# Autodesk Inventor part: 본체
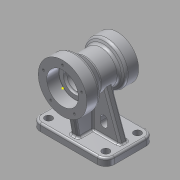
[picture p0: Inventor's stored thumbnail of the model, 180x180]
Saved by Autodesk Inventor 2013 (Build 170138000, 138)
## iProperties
Created: 2015-08
Part Number: 본체
Material: 알루미늄 6061
Document SubType Name: Modeling
Designer: ST4
Density: 2.71 g/cm^3
Mass: 1055 g
Surface Area: 768.882 cm^2
Volume: 389.298 cm^3
Author: ST4
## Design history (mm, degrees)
sketch "스케치1"
  geometry: 1 further point
sketch "스케치2"
  geometry: L1 (0, 0)-(90, 0); L2 (0, 26)-(0, 40); L3 (0, 40)-(20, 40); L4 (20, 40)-(35.493, 27); L5 (35.493, 27)-(65.381, 27); L6 (65.381, 27)-(70, 35); L7 (70, 35)-(90, 35); L8 (90, 35)-(90, 20); L9 (90, 20)-(73, 20); L10 (73, 20)-(73, 16); L11 (73, 16)-(23, 16); L12 (23, 16)-(23, 19); L13 (23, 19)-(20, 19); L14 (20, 19)-(20, 26); L15 (20, 26)-(0, 26)
  constraints: 30 end point, 8 parallel, 4 perpendicular, 1 horizontal
  dimensions: "d0" = 90 distance of L1.start L1.end; "d2" = 32 diameter of L11 L1; "d3" = 38 diameter of L13 L1; "d4" = 52 diameter of L15 L1; "d5" = 40 diameter of L9 L1; "d6" = 17 distance between parallel lines of L8 L10; "d7" = 20 distance between parallel lines of L2 L14; "d8" = 3 distance between parallel lines of L14 L12; "d9" = 0 distance from line of L1.start L2; "d10" = 90 distance between parallel lines of L2 L8; "d11" = 20 distance from line of L2 L3.end; "d12" = 20 distance of L7.end L6.end; "d13" = 60 deg angle of L7 L6; "d14" = 40 deg angle of L3 L4; "d15" = 80 diameter of L3 L1; "d16" = 70 diameter of L7 L1; "d17" = 54 diameter of L5 L1
revolve "회전1" sketch "스케치2" stored, may be unused: angle "d18" = 90 deg
node "작업 평면1"
sketch "스케치3"
  geometry: L1 (-61, 90)-(61, 90); L2 (61, 90)-(61, 10); L3 (61, 10)-(-61, 10); L4 (-61, 10)-(-61, 90); L5 (20, 90)-(-20, 90) reference; 1 further point
  constraints: 8 end point, 2 parallel, 1 horizontal, 1 perpendicular
  dimensions: "d21" = 80 distance between parallel lines of L3 L1; "d22" = 122 distance between parallel lines of L2 L4; "d23" = 61 distance from line of point (0, 0) L4; "d24" = 0 distance between parallel lines of L5 L1
extrude "돌출1" join sketch "스케치3" distance "d25" = 12; taper "d26" = 0 deg
fillet "모깎기1" dims "d27" = 14
sketch "스케치4"
  geometry: C1 r 6 at (-47, 76); C2 r 6 at (47, 76); C3 r 6 at (47, 24); C4 r 6 at (-47, 24); A1 r 14 centre (-47, 76) between (-47, 90) and (-61, 76) reference; A2 r 14 centre (-47, 24) between (-61, 24) and (-47, 10) reference; A3 r 14 centre (47, 24) between (47, 10) and (61, 24) reference; A4 r 14 centre (47, 76) between (61, 76) and (47, 90) reference; 1 further point
  constraints: 4 centre point, 4 coincident
  dimensions: "d28" = 12 diameter of C1; "d30" = 12 diameter of C4; "d31" = 12 diameter of C3; "d32" = 12 diameter of C2
extrude "돌출2" cut sketch "스케치4" stored distance "d33" = 12; taper "d34" = 0 deg
node "작업 평면2"
fillet "모깎기3" dims "d73" = 0.3
fillet "모깎기4" dims "d74" = 5
sketch "스케치8"
  geometry: L1 (0, -40)-(18.18, -40) reference; L2 (21.394, -38.83)-(34.099, -28.17) reference; L3 (37.313, -27)-(62.494, -27) reference; L4 (66.825, -29.5)-(68.557, -32.5) reference; L5 (72.887, -35)-(90, -35) reference; L6 (76, -78)-(24, -78) reference; L7 (10, -78)-(24, -78) reference; L8 (70, -78)-(82, -78) reference; L9 (76, -78)-(90, -78) reference; L10 (13.3, -40)-(20, -78); L11 (80, -35)-(80, -78); L12 (10, -90)-(10, -78) reference; A1 r 5 centre (18.18, -35) between (18.18, -40) and (21.394, -38.83) reference; A2 r 5 centre (37.313, -32) between (37.313, -27) and (34.099, -28.17) reference; A3 r 5 centre (62.494, -32) between (66.825, -29.5) and (62.494, -27) reference; A4 r 5 centre (72.887, -30) between (68.557, -32.5) and (72.887, -35) reference; 1 further point
  constraints: 4 end point, 4 point on line, 1 perpendicular
  dimensions: "d75" = 80 deg angle of L7 L10; "d76" = 10 distance from line of L12 L10.end; "d77" = 10 distance from line of L9.end L11
extrude "돌출6" join sketch "스케치8" stored distance "d78" = 12; taper "d79" = 0 deg
sketch "스케치9"
  geometry: L1 (94, 12)-(0, 12) reference; L2 (-14, 12)-(0, 12) reference; L3 (88, 12)-(100, 12) reference; L4 (94, 12)-(108, 12) reference; L5 (21.336, 81.611)-(-4, 12); L6 (72.664, 81.611)-(98, 12); L7 (-14, 0)-(-14, 12) reference; L8 (108, 12)-(108, 0) reference; L9 (0, 12)-(0, 0) reference; L10 (94, 12)-(0, 12) reference; L11 (94, 0)-(94, 12) reference; L12 (0, 0)-(94, 0) reference; L13 (6, 0)-(-6, 0) reference; L14 (-6, 12)-(6, 12) reference; L15 (-14, 12)-(0, 12) reference; L16 (0, 12)-(0, 0) reference; L17 (0, 0)-(-14, 0) reference; L18 (-14, 0)-(-14, 12) reference; L19 (100, 0)-(88, 0) reference; L20 (88, 12)-(100, 12) reference; L21 (94, 12)-(108, 12) reference; L22 (108, 12)-(108, 0) reference; L23 (108, 0)-(94, 0) reference; L24 (94, 0)-(94, 12) reference; L25 (-4, 12)-(98, 12); A1 r 27 centre (47, 90) between (47, 63) and (21.336, 81.611) reference; 1 further point
  constraints: 6 end point, 2 point on circle, 2 point on line, 1 collinear
  dimensions: "d80" = 70 deg angle of L1 L5; "d81" = 70 deg angle of L1 L6; "d82" = 10 distance from line of L7 L5.end; "d83" = 10 distance from line of L8 L6.end
extrude "돌출7" join sketch "스케치9" stored distance "d84" = 12; taper "d85" = 0 deg
sketch "스케치10" dims "d86" = 66
  geometry: C1 r 40 at (0, 0) reference; C2 r 26 at (0, 0) reference; 2 further points
  constraints: 1 coincident, 1 vertical alignment, 2 other
  dimensions: "d89" = 0 horizontal distance of C1.centre point (0, 33)
hole "구멍1" sketch "스케치10" at (0, 33) diameter "d90" = 3.459; stored, may be unused: countersink angle "d94" = 90 deg, drill point angle "d96" = 118 deg; dims "d91" = 10, "d92" = 4, "d93" = 2, "d95" = 13
sketch "스케치11" dims "d100" = 54
  geometry: C1 r 20 at (0, 0) reference; C2 r 35 at (0, 0) reference; 2 further points
  constraints: 1 coincident, 1 vertical alignment, 2 other
  dimensions: "d102" = 0 horizontal distance of C1.centre point (0, -27)
hole "구멍2" sketch "스케치11" at (0, -27) diameter "d103" = 3.459; stored, may be unused: countersink angle "d107" = 90 deg, drill point angle "d109" = 118 deg; dims "d104" = 10, "d105" = 4, "d106" = 2, "d108" = 13
fillet "모깎기5" dims "d113" = 3
fillet "모깎기6" dims "d114" = 3
fillet "모깎기7" dims "d115" = 3
fillet "모깎기8" dims "d116" = 3
sketch "스케치12"
  geometry: L1 (38, 63)-(38, 15) reference; L2 (17, 36)-(17, 30); L3 (29, 36)-(29, 30); L4 (94, 12)-(0, 12) reference; A1 r 27 centre (47, 90) between (23.047, 77.54) and (47, 63) reference; A2 r 6 centre (23, 36) between (29, 36) and (17, 36); A3 r 6 centre (23, 30) between (17, 30) and (29, 30)
  constraints: 4 end point, 4 point on circle, 2 centre point, 2 parallel, 2 tangent
  dimensions: "d117" = 0 horizontal distance of A3.centre A2.centre; "d119" = 6 distance of A3.centre A2.centre; "d122" = 6 radius of A2; "d123" = 6 radius of A3; "d124" = 18 distance from line of L4 A3.centre; "d125" = 24 horizontal distance of A1.centre A3.centre
extrude "돌출8" cut sketch "스케치12" stored distance "d126" = 12; taper "d127" = 0 deg
fillet "모깎기9" dims "d128" = 3
sketch "스케치13"
  geometry: L1 (-78, 87)-(-78, 76) reference; L2 (-35, 80)-(-75, 80) reference; L3 (-74.739, 67.002)-(-33.261, 67.002); L4 (-33.261, 67.002)-(-33.261, 60.998); L5 (-33.261, 60.998)-(-74.739, 60.998); L6 (-74.739, 60.998)-(-74.739, 67.002); L7 (-33.261, 64)-(-74.739, 64); L8 (-54, 67.002)-(-54, 60.998); 1 further point
  constraints: 4 end point, 4 midpoint, 2 other
  dimensions: "d134" = 24 distance between parallel lines of L1 L8; "d135" = 16 distance between parallel lines of L2 L7
extrude "돌출9" join sketch "스케치13" distance "d136" = 0.5; taper "d137" = 0 deg
node "솔리드1"
pattern_circular "원형 패턴1" dims angle "d98" = 360 deg
pattern_circular "원형 패턴2" dims angle "d111" = 360 deg
mirror "대칭2"
node "투영된 루프2"
node "투영된 루프3"
node "투영된 루프4"
node "투영된 루프5"
node "투영된 루프6"
other parameters: "d54" = 12, "d56" = 12, "d61" = 12, "d62" = 12, "d120" = 12, "d121" = 12
